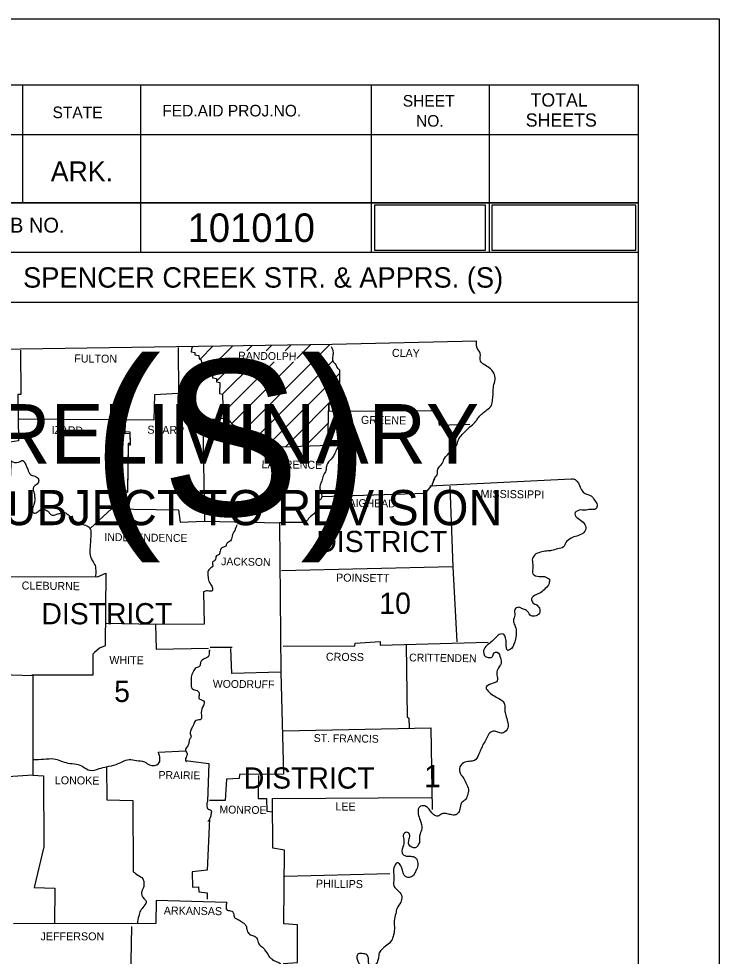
# Model space of a CAD drawing. Extents: x 1369885 to 1370219, y 379980 to 380218.
# Drawn here: x 1370177.5 to 1370218.7, y 380162.7 to 380217.9 of the extents above; entities that cross this region are included whole.
import ezdxf

# ---------------------------------------------------------------- set-up
doc = ezdxf.new("R2010")
doc.units = 0
for name, color, linetype in [('Default', 7, 'Continuous'), ('Level 2', 7, 'Continuous'), ('R_No Plot', 7, 'Continuous'), ('R_Striping', 7, 'Continuous'), ('STAMP_PE_FOSTER', 7, 'Continuous'), ('STAMP_PE_FOSTER-SIGNATURE', 7, 'Continuous'), ('STAMP_PE_TAEGTMEYER', 7, 'Continuous'), ('Total Pages', 7, 'Continuous')]:
    doc.layers.add(name, color=color, linetype=linetype)

msp = doc.modelspace()

# ---------------------------------------------------------------- linework, layer by layer
at = {"layer": 'Default'}
for p, q in [((1370196.378, 380197.256), (1370196.398, 380195.363)), ((1370201.828, 380190.402), (1370201.957, 380190.811)), ((1370201.858, 380190.532), (1370201.997, 380190.85)), ((1370188.767, 380180.908), (1370190.072, 380180.908))]:
    msp.add_line(p, q, dxfattribs=at)
msp.add_lwpolyline([(1370198.453, 380204.297), (1370204.983, 380204.297), (1370204.983, 380206.938), (1370198.453, 380206.938)], close=True, dxfattribs=at)
for points in [[(1370144.335, 380198.452), (1370162.058, 380198.442), (1370177.609, 380198.482), (1370195.96, 380198.761), (1370204.458, 380198.96)], [(1370177.609, 380198.412), (1370177.629, 380195.802), (1370177.45, 380195.792), (1370177.48, 380193.062), (1370176.713, 380192.952), (1370176.772, 380192.215), (1370177.041, 380191.876), (1370177.021, 380191.02), (1370175.527, 380190.96), (1370175.477, 380189.625), (1370174.112, 380189.575), (1370174.053, 380187.961), (1370174.122, 380187.822), (1370174.162, 380185.241), (1370176.503, 380185.082), (1370176.473, 380179.314), (1370178.336, 380179.254), (1370178.336, 380173.386), (1370176.862, 380173.277), (1370176.752, 380171.981), (1370174.292, 380171.972)], [(1370186.894, 380198.571), (1370186.914, 380195.861), (1370185.489, 380195.782), (1370185.45, 380194.287), (1370177.519, 380194.337)], [(1370187.681, 380198.561), (1370187.651, 380198.302), (1370187.87, 380198.272), (1370187.86, 380198.133), (1370188.11, 380198.083), (1370188.129, 380197.904), (1370188.249, 380197.834), (1370188.289, 380197.306), (1370188.907, 380197.236), (1370188.907, 380196.768), (1370189.136, 380196.738), (1370189.136, 380196.549), (1370189.335, 380196.499), (1370189.325, 380195.861), (1370189.504, 380195.822), (1370189.544, 380194.387), (1370188.608, 380194.307), (1370188.628, 380193.998), (1370188.339, 380193.989), (1370188.438, 380188.33), (1370192.852, 380188.23), (1370192.931, 380179.443), (1370190.052, 380179.364), (1370189.992, 380180.848)], [(1370195.691, 380192.932), (1370195.751, 380195.224), (1370195.751, 380194.815), (1370202.157, 380194.845), (1370202.246, 380193.998), (1370204.049, 380194.058)], [(1370183.756, 380194.257), (1370183.736, 380193.62), (1370184.045, 380193.6), (1370184.055, 380192.903), (1370183.945, 380192.903), (1370183.905, 380190.143), (1370183.646, 380190.023), (1370183.646, 380189.107)], [(1370183.756, 380194.158), (1370183.736, 380193.52), (1370184.045, 380193.5), (1370184.055, 380192.803), (1370183.945, 380192.803), (1370183.905, 380190.043), (1370183.646, 380189.934), (1370183.646, 380189.007)], [(1370185.131, 380194.238), (1370185.141, 380194.248)], [(1370192.334, 380192.693), (1370196.408, 380192.833)], [(1370210.027, 380190.82), (1370201.708, 380190.392)], [(1370195.362, 380189.794), (1370201.449, 380189.994), (1370201.808, 380190.412)], [(1370202.884, 380190.392), (1370203.063, 380185.64), (1370203.282, 380181.227)], [(1370181.724, 380187.931), (1370182.969, 380189.067), (1370186.914, 380189.007), (1370186.994, 380188.27), (1370188.428, 380188.33)], [(1370194.286, 380188.25), (1370192.951, 380188.25), (1370192.852, 380188.23)], [(1370203.063, 380185.64), (1370192.971, 380185.411)], [(1370176.503, 380185.082), (1370182.132, 380185.052), (1370182.62, 380185.281), (1370182.59, 380180.998), (1370182.252, 380180.858), (1370181.963, 380180.599), (1370181.863, 380180.509), (1370181.853, 380179.274), (1370178.267, 380179.274)], [(1370188.379, 380184.185), (1370188.408, 380182.263), (1370185.559, 380182.253), (1370182.63, 380182.303)], [(1370185.559, 380182.253), (1370185.599, 380180.808), (1370188.677, 380180.868)], [(1370193.061, 380180.978), (1370197.295, 380180.998), (1370197.305, 380181.157), (1370198.769, 380181.257), (1370198.769, 380181.027), (1370205.145, 380181.207)], [(1370188.767, 380180.729), (1370188.707, 380180.719)], [(1370200.304, 380181.027), (1370200.363, 380176.813), (1370200.463, 380176.744), (1370200.493, 380176.176)], [(1370192.931, 380179.443), (1370193.091, 380173.436), (1370190.491, 380173.426), (1370190.481, 380173.187), (1370189.723, 380173.137), (1370189.654, 380171.892), (1370188.737, 380171.892)], [(1370193.061, 380175.986), (1370201.758, 380176.166)], [(1370201.758, 380176.166), (1370201.848, 380171.364)], [(1370185.729, 380174.741), (1370187.322, 380174.821)], [(1370187.322, 380174.243), (1370188.687, 380174.074), (1370188.608, 380171.832)], [(1370182.66, 380173.884), (1370182.68, 380171.922), (1370184.224, 380171.892), (1370184.244, 380167.688)], [(1370178.336, 380173.386), (1370178.964, 380173.336), (1370178.984, 380169.152), (1370178.406, 380166.771), (1370179.622, 380166.721), (1370179.611, 380164.628)], [(1370191.606, 380173.366), (1370191.596, 380172.011), (1370192.094, 380172.011), (1370192.114, 380171.254), (1370192.433, 380171.224)], [(1370193.061, 380162.288), (1370193.918, 380162.348), (1370193.908, 380164.569), (1370193.111, 380164.629), (1370193.151, 380168.973), (1370192.463, 380169.072), (1370192.433, 380172.001), (1370201.788, 380172.071)], [(1370188.737, 380170.786), (1370188.598, 380167.787), (1370187.701, 380167.688), (1370187.721, 380166.791), (1370188.09, 380166.811), (1370188.1, 380166.502), (1370188.588, 380166.442), (1370188.598, 380166.084)], [(1370193.17, 380167.429), (1370199.347, 380167.588)], [(1370189.743, 380165.884), (1370185.599, 380165.994), (1370185.579, 380164.649), (1370177.191, 380164.619)], [(1370184.144, 380164.47), (1370184.055, 380160.345), (1370185.579, 380160.216)]]:
    msp.add_lwpolyline(points, dxfattribs=at)
for points in [[(1370201.947, 380190.761), (1370201.957, 380190.811), (1370202.127, 380191.07), (1370202.176, 380191.398), (1370202.436, 380191.737), (1370202.565, 380192.036), (1370202.824, 380192.335), (1370203.023, 380192.554), (1370203.272, 380192.793), (1370203.382, 380193.132), (1370203.611, 380193.441), (1370203.85, 380193.68), (1370204.129, 380193.949), (1370204.418, 380194.218), (1370204.577, 380194.457), (1370204.807, 380194.686), (1370205.066, 380194.885), (1370205.325, 380195.154), (1370205.394, 380195.493), (1370205.434, 380195.871), (1370205.454, 380196.3), (1370205.544, 380196.678), (1370205.474, 380197.057), (1370205.195, 380197.376), (1370204.876, 380197.565), (1370204.687, 380197.764), (1370204.667, 380198.223), (1370204.518, 380198.482), (1370204.458, 380198.96)], [(1370195.9, 380198.621), (1370196, 380198.342), (1370195.99, 380198.053), (1370195.99, 380197.774), (1370196.129, 380197.595), (1370196.269, 380197.356), (1370196.378, 380197.256)], [(1370196.398, 380195.363), (1370196.249, 380195.224), (1370195.98, 380195.224), (1370195.751, 380195.224)], [(1370189.664, 380194.487), (1370189.903, 380194.238), (1370190.112, 380194.028), (1370190.351, 380193.909), (1370190.64, 380193.739), (1370190.889, 380193.61), (1370191.058, 380193.401), (1370191.288, 380193.172), (1370191.517, 380192.992), (1370191.875, 380192.813), (1370191.995, 380192.624), (1370192.164, 380192.395), (1370192.334, 380192.693)], [(1370196.368, 380192.823), (1370196.209, 380192.564), (1370196.079, 380192.255), (1370195.81, 380191.906), (1370195.611, 380191.558), (1370195.581, 380191.329), (1370195.432, 380191.03), (1370195.342, 380190.721), (1370195.243, 380190.452), (1370195.243, 380190.183), (1370195.322, 380189.904), (1370195.302, 380189.655), (1370195.133, 380189.535), (1370195.093, 380189.217), (1370195.023, 380188.997), (1370194.884, 380188.778), (1370194.675, 380188.619), (1370194.456, 380188.36), (1370194.286, 380188.25)], [(1370177.041, 380191.876), (1370177.48, 380191.807), (1370177.739, 380191.906), (1370177.928, 380191.617), (1370178.028, 380191.398), (1370178.187, 380191.079), (1370178.456, 380190.98), (1370178.655, 380190.811), (1370178.655, 380190.621), (1370178.476, 380190.442), (1370178.346, 380190.273), (1370178.386, 380190.063), (1370178.436, 380189.774), (1370178.436, 380189.505), (1370178.366, 380189.246), (1370178.306, 380189.017), (1370178.366, 380188.828), (1370178.575, 380188.858), (1370178.795, 380189.017), (1370179.024, 380189.017), (1370179.243, 380188.898), (1370179.472, 380188.689), (1370179.701, 380188.738), (1370179.891, 380188.788), (1370180.15, 380188.868), (1370180.339, 380188.768), (1370180.498, 380188.639), (1370180.697, 380188.429), (1370180.887, 380188.3), (1370181.126, 380188.18), (1370181.425, 380188.101), (1370181.694, 380187.911), (1370181.744, 380187.593), (1370181.734, 380187.324), (1370181.714, 380186.985), (1370181.684, 380186.606), (1370181.724, 380186.248), (1370181.843, 380186.009), (1370181.993, 380185.72), (1370182.032, 380185.461), (1370182.022, 380185.042)], [(1370210.027, 380190.82), (1370210.146, 380190.83), (1370210.515, 380190.432), (1370210.684, 380190.103), (1370210.924, 380189.924), (1370211.202, 380189.824), (1370211.402, 380189.565), (1370211.551, 380189.296), (1370211.471, 380189.057), (1370211.163, 380189.027), (1370210.824, 380188.977), (1370210.495, 380188.987), (1370210.236, 380188.768), (1370210.475, 380188.469), (1370210.794, 380188.2), (1370210.884, 380187.901), (1370210.704, 380187.613), (1370210.356, 380187.463), (1370210.017, 380187.334), (1370209.708, 380187.075), (1370209.569, 380186.816), (1370209.23, 380186.706), (1370208.871, 380186.606), (1370208.572, 380186.576), (1370208.214, 380186.507), (1370207.875, 380186.347), (1370207.736, 380186.058), (1370207.775, 380185.66), (1370207.765, 380185.232), (1370208.134, 380185.082), (1370208.453, 380185.072), (1370208.752, 380184.913)], [(1370190.341, 380188.131), (1370190.212, 380187.792), (1370190.062, 380187.463), (1370189.963, 380187.174), (1370189.753, 380187.015), (1370189.684, 380186.865), (1370189.504, 380186.796), (1370189.355, 380186.576), (1370189.295, 380186.377), (1370189.136, 380186.288), (1370189.066, 380186.048), (1370188.916, 380185.919), (1370188.926, 380185.7), (1370188.767, 380185.55), (1370188.638, 380185.371), (1370188.638, 380185.132), (1370188.687, 380184.813), (1370188.797, 380184.624), (1370188.897, 380184.385), (1370188.887, 380184.235), (1370188.608, 380184.235), (1370188.379, 380184.185)], [(1370208.752, 380184.913), (1370208.722, 380184.674), (1370208.493, 380184.365), (1370208.214, 380184.126), (1370207.945, 380184.006), (1370207.696, 380183.767), (1370207.775, 380183.538), (1370208.014, 380183.388), (1370208.174, 380183.139), (1370208.154, 380182.91), (1370207.885, 380182.741), (1370207.606, 380182.811), (1370207.397, 380183.08), (1370207.158, 380183.169), (1370206.949, 380183.269), (1370206.709, 380183.129), (1370206.709, 380182.811), (1370206.62, 380182.472), (1370206.699, 380182.213), (1370206.789, 380181.864), (1370206.779, 380181.605), (1370206.699, 380181.227), (1370206.51, 380180.848), (1370206.291, 380180.729), (1370206.201, 380181.137), (1370206.161, 380181.476), (1370206.022, 380181.675), (1370205.853, 380181.685), (1370205.623, 380181.525), (1370205.364, 380181.276), (1370205.046, 380180.998), (1370204.866, 380180.729), (1370204.966, 380180.38), (1370205.205, 380180.3), (1370205.394, 380180.36), (1370205.484, 380180.579), (1370205.673, 380180.619), (1370205.853, 380180.28)], [(1370188.707, 380180.719), (1370188.657, 380180.35), (1370188.448, 380180.25), (1370188.209, 380180.011), (1370188.149, 380179.792), (1370187.95, 380179.702), (1370187.771, 380179.473), (1370187.651, 380179.154), (1370187.651, 380178.826), (1370187.721, 380178.457), (1370188, 380178.357), (1370188.129, 380178.138), (1370188.11, 380177.909), (1370188.369, 380177.75), (1370188.418, 380177.62), (1370188.369, 380177.481), (1370188.249, 380177.072), (1370188.259, 380176.803), (1370188.239, 380176.684), (1370187.94, 380176.604), (1370187.771, 380176.305), (1370187.651, 380176.096), (1370187.601, 380175.827), (1370187.641, 380175.628), (1370187.552, 380175.478), (1370187.512, 380175.249), (1370187.412, 380175.05), (1370187.313, 380174.861), (1370187.422, 380174.641), (1370187.382, 380174.492), (1370187.322, 380174.243), (1370187.372, 380174.173)], [(1370205.853, 380180.28), (1370205.892, 380179.961), (1370205.703, 380179.623), (1370205.643, 380179.274), (1370205.673, 380178.935), (1370205.325, 380178.756), (1370205.016, 380178.537), (1370205.195, 380178.268), (1370205.524, 380178.029), (1370205.853, 380177.839), (1370206.062, 380177.66), (1370206.112, 380177.212), (1370206.171, 380176.923), (1370206.281, 380176.524), (1370206.321, 380176.255), (1370206.122, 380175.927), (1370205.892, 380175.857), (1370205.653, 380175.937), (1370205.364, 380175.956), (1370205.135, 380175.737), (1370204.976, 380175.428), (1370204.807, 380175.12), (1370204.687, 380174.861), (1370204.567, 380174.582), (1370204.328, 380174.243), (1370204.029, 380174.193), (1370203.681, 380174.103), (1370203.472, 380173.864), (1370203.501, 380173.456), (1370203.701, 380173.187), (1370203.86, 380172.848), (1370203.97, 380172.549), (1370203.91, 380172.181), (1370203.761, 380171.902), (1370203.561, 380171.742), (1370203.472, 380171.384), (1370203.332, 380171.125), (1370203.203, 380171.035), (1370202.934, 380171.055), (1370202.655, 380171.115), (1370202.406, 380171.095), (1370202.176, 380170.975), (1370201.947, 380171.045), (1370201.708, 380171.314), (1370201.509, 380171.513), (1370201.29, 380171.583), (1370201.061, 380171.463), (1370201.021, 380171.105), (1370201.13, 380170.726), (1370201.23, 380170.228), (1370201.13, 380169.919), (1370201.091, 380169.411)], [(1370178.356, 380174.303), (1370178.964, 380174.323), (1370179.572, 380174.343), (1370179.96, 380174.233), (1370180.399, 380174.094), (1370180.907, 380174.024), (1370181.275, 380173.884), (1370181.694, 380173.665), (1370182.242, 380173.765), (1370182.67, 380173.874), (1370183.228, 380174.014), (1370183.597, 380174.173), (1370184.005, 380174.303), (1370184.423, 380174.243), (1370184.902, 380174.163), (1370185.191, 380173.984), (1370185.729, 380174.064), (1370185.729, 380174.741)], [(1370188.608, 380171.832), (1370188.568, 380171.613), (1370188.657, 380171.384), (1370188.807, 380171.314), (1370188.827, 380171.095), (1370188.777, 380170.876), (1370188.737, 380170.786), (1370188.638, 380170.656)], [(1370201.091, 380169.411), (1370200.842, 380169.102), (1370200.473, 380169.292), (1370200.473, 380169.561), (1370200.523, 380169.83), (1370200.393, 380170.009), (1370200.164, 380169.929), (1370200.164, 380169.591), (1370200.144, 380169.262), (1370200.074, 380168.794), (1370200.224, 380168.644), (1370200.582, 380168.604), (1370200.832, 380168.534), (1370200.981, 380168.285), (1370200.971, 380167.977), (1370200.851, 380167.688), (1370200.682, 380167.439), (1370200.403, 380167.359), (1370200.184, 380167.498), (1370200.094, 380167.787), (1370199.995, 380168.036), (1370199.815, 380168.226), (1370199.616, 380168.016), (1370199.566, 380167.628), (1370199.586, 380167.299), (1370199.586, 380166.851), (1370199.865, 380166.552), (1370200.045, 380166.213), (1370199.985, 380165.904), (1370199.776, 380165.546), (1370199.696, 380165.227), (1370199.606, 380164.799), (1370199.616, 380164.33), (1370199.536, 380163.872), (1370199.387, 380163.563), (1370199.098, 380163.314), (1370198.909, 380163.145), (1370198.759, 380162.985), (1370198.68, 380162.657), (1370198.63, 380162.428), (1370198.421, 380162.149), (1370198.251, 380162.129), (1370198.122, 380162.238), (1370198.082, 380162.428), (1370198.082, 380162.607), (1370197.992, 380162.796), (1370197.723, 380162.876), (1370197.504, 380162.866), (1370197.404, 380162.706), (1370197.544, 380162.278), (1370197.594, 380162.009), (1370197.524, 380161.631), (1370197.564, 380161.591), (1370197.175, 380161.381), (1370196.857, 380161.352), (1370196.588, 380161.272), (1370196.339, 380161.112), (1370196.219, 380160.863), (1370196.04, 380160.674), (1370195.89, 380160.485), (1370195.681, 380160.395)], [(1370184.244, 380167.688), (1370184.513, 380167.498), (1370184.802, 380167.279), (1370184.872, 380166.98), (1370184.852, 380166.771), (1370184.762, 380166.602), (1370184.742, 380166.323), (1370184.872, 380166.124), (1370185.001, 380165.964), (1370184.872, 380165.665), (1370184.663, 380165.396), (1370184.563, 380165.087), (1370184.483, 380164.629)], [(1370189.743, 380165.884), (1370189.773, 380165.436), (1370190.042, 380165.366), (1370190.142, 380165.247), (1370190.202, 380164.998), (1370190.391, 380164.888), (1370190.64, 380164.739), (1370190.789, 380164.629), (1370190.899, 380164.45), (1370190.969, 380164.161), (1370191.148, 380163.982), (1370191.387, 380163.892), (1370191.557, 380163.683), (1370191.666, 380163.384), (1370191.845, 380163.254), (1370192.025, 380163.025), (1370192.104, 380162.926), (1370192.264, 380162.667), (1370192.413, 380162.537), (1370192.523, 380162.457), (1370192.702, 380162.398), (1370192.921, 380162.258), (1370193.061, 380162.039), (1370193.061, 380161.88), (1370193.011, 380161.621), (1370192.961, 380161.362), (1370192.941, 380161.063), (1370192.921, 380160.804), (1370193.021, 380160.584), (1370192.961, 380160.256), (1370192.852, 380160.076), (1370192.842, 380159.837), (1370192.812, 380159.479), (1370192.762, 380159.269), (1370192.672, 380158.931), (1370192.523, 380158.751)]]:
    msp.add_spline(points, degree=3, dxfattribs=at)
at = {"layer": 'R_No Plot'}
msp.add_line((1369885.407, 380217.922), (1370218.741, 380217.922), dxfattribs=at)
msp.add_lwpolyline([(1369885.401, 380217.922), (1370218.741, 380217.922), (1370218.741, 380004.585), (1369885.401, 380004.585)], close=True, dxfattribs=at)
at = {"layer": 'R_Striping'}
for p, q in [((1370187.676, 380198.515), (1370187.797, 380198.636)), ((1370188.171, 380197.879), (1370188.946, 380198.654)), ((1370188.685, 380197.261), (1370190.095, 380198.671)), ((1370190.76, 380193.68), (1370195.819, 380198.739)), ((1370190.93, 380198.376), (1370191.243, 380198.689)), ((1370192.062, 380198.376), (1370192.392, 380198.706)), ((1370193.193, 380198.376), (1370193.541, 380198.724)), ((1370193.868, 380197.919), (1370194.69, 380198.741)), ((1370189.136, 380196.581), (1370190.354, 380197.8)), ((1370189.504, 380195.818), (1370191.412, 380197.726)), ((1370189.535, 380194.718), (1370192.543, 380197.726)), ((1370190.042, 380194.093), (1370193.675, 380197.726)), ((1370191.339, 380193.127), (1370195.989, 380197.778)), ((1370191.984, 380192.641), (1370196.381, 380197.038)), ((1370193.197, 380192.723), (1370196.392, 380195.918)), ((1370194.369, 380192.763), (1370195.722, 380194.116)), ((1370195.54, 380192.803), (1370195.692, 380192.955)), ((1370195.686, 380192.808), (1370195.688, 380192.809)), ((1370192.163, 380192.396), (1370192.263, 380192.496))]:
    msp.add_line(p, q, dxfattribs=at)
at = {"layer": 'STAMP_PE_FOSTER-SIGNATURE'}
for p, q in [((1369897.808, 380214.028), (1370213.988, 380214.028)), ((1370177.728, 380214.028), (1370177.728, 380207.088)), ((1370184.668, 380214.028), (1370184.668, 380204.148)), ((1370198.248, 380214.028), (1370198.248, 380204.148)), ((1370205.188, 380214.028), (1370205.188, 380204.148)), ((1370213.988, 380008.568), (1370213.988, 380214.028)), ((1370213.988, 380211.088), (1370170.888, 380211.088)), ((1370213.988, 380211.108), (1370213.988, 380211.108)), ((1370213.988, 380207.088), (1370170.888, 380207.088)), ((1370173.848, 380207.088), (1370213.988, 380207.088)), ((1370213.988, 380204.148), (1370131.728, 380204.148)), ((1370170.888, 380201.228), (1370213.988, 380201.228))]:
    msp.add_line(p, q, dxfattribs=at)
at = {"layer": 'Total Pages'}
msp.add_lwpolyline([(1370205.352, 380204.297), (1370213.824, 380204.297), (1370213.824, 380206.938), (1370205.352, 380206.938)], close=True, dxfattribs=at)

# ---------------------------------------------------------------- texts
at = {"layer": 'Default'}
for s, height, rotation, p in [('RANDOLPH', 0.4603, 359.2583, (1370190.421, 380197.854)), ('CLAY', 0.4711, 359.2258, (1370199.467, 380198.013)), ('FULTON', 0.4711, 359.4996, (1370180.767, 380197.685)), ('GREENE', 0.4713, 359.2361, (1370197.644, 380194.068)), ('IZARD', 0.4601, 358.9258, (1370179.432, 380193.48)), ('SHARP', 0.4711, 359.3905, (1370185.071, 380193.49)), ('LAWRENCE', 0.4713, 359.2678, (1370191.796, 380191.458)), ('MISSISSIPPI', 0.47114, 359.3097, (1370204.687, 380189.715)), ('CRAIGHEAD', 0.4603, 359.1159, (1370196.03, 380189.197)), ('INDEPENDENCE', 0.46015, 359.2187, (1370182.541, 380187.174)), ('JACKSON', 0.4601, 359.1352, (1370189.415, 380185.74)), ('POINSETT', 0.4711, 359.1987, (1370196.179, 380184.783)), ('CLEBURNE', 0.4711, 359.2535, (1370177.669, 380184.315)), ('CROSS', 0.4711, 359.3839, (1370195.581, 380180.121)), ('WHITE', 0.4713, 359.3139, (1370182.829, 380179.932)), ('CRITTENDEN', 0.4603, 359.213, (1370200.483, 380180.081)), ('WOODRUFF', 0.4601, 359.2748, (1370188.926, 380178.537)), ('ST. FRANCIS', 0.46015, 359.2216, (1370194.864, 380175.339)), ('PRAIRIE', 0.4603, 359.2116, (1370185.729, 380173.167)), ('LONOKE', 0.4713, 359.4974, (1370179.622, 380172.848)), ('LEE', 0.4713, 359.4327, (1370196.139, 380171.304)), ('MONROE', 0.4601, 359.0331, (1370189.315, 380171.135)), ('PHILLIPS', 0.4711, 359.3179, (1370194.994, 380166.761)), ('ARKANSAS', 0.4711, 359.2678, (1370186.037, 380165.177))]:
    msp.add_text(s, height=height, rotation=rotation, dxfattribs=at).set_placement(p)
for s, height, p in [('DISTRICT', 1.2493, (1370195.023, 380186.517)), ('10', 1.2493, (1370198.729, 380182.88)), ('DISTRICT', 1.2493, (1370178.834, 380182.263)), ('5', 1.249, (1370183.118, 380177.69)), ('1', 1.315, (1370201.36, 380172.669)), ('DISTRICT', 1.2493, (1370190.75, 380172.589)), ('JEFFERSON', 0.4712, (1370178.785, 380163.653))]:
    msp.add_text(s, height=height, dxfattribs=at).set_placement(p)
at = {"layer": 'Level 2'}
msp.add_text('SPENCER CREEK STR. & APPRS. (S)', height=9.16, dxfattribs=at).set_placement((1369982.371, 380188.67))
at = {"layer": 'STAMP_PE_FOSTER'}
for s, height, p in [('101010', 1.68, (1370187.443, 380204.778)), ('SPENCER CREEK STR. & APPRS. (S)', 1.2, (1370177.754, 380202.088))]:
    msp.add_text(s, height=height, dxfattribs=at).set_placement(p)
at = {"layer": 'STAMP_PE_FOSTER-SIGNATURE'}
for s, height, p in [('SHEET', 0.684, (1370200.108, 380212.748)), ('TOTAL', 0.7819, (1370207.628, 380212.748)), ('STATE', 0.684, (1370179.488, 380212.068)), ('FED.AID PROJ.NO.', 0.684, (1370185.948, 380212.168)), ('NO.', 0.684, (1370200.888, 380211.568)), ('SHEETS', 0.7819, (1370207.348, 380211.568)), ('ARK.', 1.1723, (1370179.388, 380208.348)), ('JOB NO.', 0.8792, (1370175.488, 380205.328))]:
    msp.add_text(s, height=height, dxfattribs=at).set_placement(p)
at = {"layer": 'STAMP_PE_TAEGTMEYER'}
for s, height, p in [('PRELIMINARY', 3.5, (1370172.871, 380191.728)), ('SUBJECT TO REVISION', 2.07511, (1370174.68, 380188.099))]:
    msp.add_text(s, height=height, dxfattribs=at).set_placement(p)

doc.saveas('drawing.dxf')
